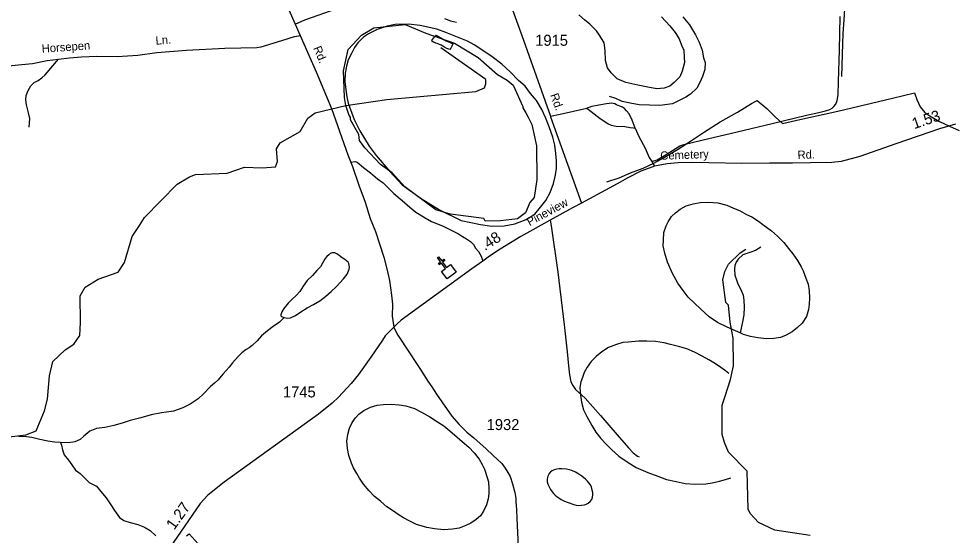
# Model space of a CAD drawing. Extents: x 2206922 to 2357709, y 510027 to 673830.
# Drawn here: x 2306591 to 2317208, y 526957 to 532816 of the extents above; entities that cross this region are included whole.
import ezdxf

# ---------------------------------------------------------------- set-up
doc = ezdxf.new("R2010")
doc.units = 0
for name, color, linetype in [('Exist Cultural Church CELL', 7, 'Continuous'), ('Exist Hydrographic Creek Single Shore', 7, 'Continuous'), ('Exist Hydrographic Misc Water Feature', 7, 'Continuous'), ('Exist Hydrographic Pond Under 1500 Sq Ft', 7, 'Continuous'), ('Exist Road Non-System Type 51', 7, 'Continuous'), ('Exist Road Non-System Type 51 Label', 7, 'Continuous'), ('Exist Road Secondary Mileage Hundredths English Label', 7, 'Continuous'), ('Exist Road Secondary Type 51 Attributed', 7, 'Continuous'), ('Exist Road Secondary Type 51 Label', 7, 'Continuous'), ('Exist Road Secondary Type 51 Number Label', 7, 'Continuous')]:
    doc.layers.add(name, color=color, linetype=linetype)

msp = doc.modelspace()

# ---------------------------------------------------------------- linework, layer by layer
at = {"layer": 'Exist Cultural Church CELL'}
msp.add_lwpolyline([(2311388, 529950), (2311433, 529984), (2311388, 530045), (2311362, 530026), (2311353, 530039), (2311378, 530058), (2311342, 530106), (2311355, 530116), (2311391, 530068), (2311416, 530087), (2311426, 530074), (2311401, 530055), (2311446, 529994), (2311492, 530029), (2311556, 529943), (2311452, 529865)], close=True, dxfattribs=at)
at = {"layer": 'Exist Hydrographic Creek Single Shore'}
msp.add_lwpolyline([(2306388, 528063), (2306671, 528097), (2306788, 528141), (2306885, 528368), (2306917, 528501), (2306939, 528767), (2306979, 528926), (2307119, 529060), (2307218, 529126), (2307284, 529221), (2307291, 529369), (2307287, 529671), (2307345, 529771), (2307494, 529863), (2307718, 529941), (2307791, 530052), (2307880, 530344), (2307962, 530469), (2308019, 530560), (2308390, 530939), (2308530, 531023), (2308597, 531049), (2308955, 531064), (2309154, 531131), (2309354, 531126), (2309504, 531135), (2309528, 531195), (2309518, 531342), (2309559, 531409), (2309783, 531537), (2309873, 531688), (2309955, 531747), (2310304, 531833)], dxfattribs=at)
at = {"layer": 'Exist Hydrographic Misc Water Feature'}
for points in [[(2315975, 533192), (2315957, 532856), (2315945, 532650), (2315936, 532414), (2315930, 532160)], [(2313886, 532837), (2313981, 532736), (2314042, 532661), (2314085, 532588), (2314113, 532516), (2314140, 532460), (2314141, 532378), (2314145, 532318), (2314121, 532220), (2314093, 532158), (2314028, 532093), (2313979, 532051), (2313917, 532028), (2313831, 532021), (2313729, 532038), (2313617, 532061), (2313482, 532093), (2313382, 532134), (2313315, 532204), (2313273, 532259), (2313250, 532343), (2313246, 532455), (2313234, 532544), (2313183, 532630), (2313148, 532680), (2313071, 532755), (2313013, 532802), (2312949, 532861)], [(2314128, 532836), (2314203, 532745), (2314272, 532634), (2314313, 532550), (2314348, 532461), (2314363, 532371), (2314381, 532319), (2314376, 532241), (2314351, 532159), (2314320, 532092), (2314287, 532030), (2314213, 531961), (2314162, 531927), (2314078, 531884), (2314009, 531851), (2313865, 531830), (2313749, 531834), (2313633, 531841), (2313531, 531858), (2313439, 531877), (2313368, 531910), (2313296, 531934)], [(2310343, 531816), (2310372, 531744), (2310398, 531674), (2310460, 531543), (2310566, 531372), (2310649, 531263), (2310803, 531083), (2310944, 530933), (2311158, 530775), (2311367, 530649), (2311610, 530528), (2311831, 530481), (2311959, 530462), (2312099, 530467), (2312222, 530491), (2312350, 530538), (2312447, 530599), (2312512, 530678), (2312571, 530754), (2312622, 530843), (2312661, 530947), (2312680, 531027), (2312693, 531115), (2312694, 531205), (2312688, 531289), (2312676, 531383), (2312653, 531473), (2312610, 531588), (2312569, 531696), (2312528, 531787), (2312465, 531887), (2312400, 531966), (2312337, 532051), (2312263, 532116), (2312168, 532213), (2312073, 532302), (2311964, 532383), (2311857, 532456), (2311761, 532519), (2311682, 532560), (2311552, 532614), (2311439, 532661), (2311335, 532696), (2311145, 532738), (2311014, 532756), (2310863, 532751), (2310773, 532730), (2310657, 532695), (2310562, 532646), (2310504, 532607), (2310439, 532544), (2310402, 532488), (2310366, 532422), (2310329, 532349), (2310312, 532277), (2310295, 532197), (2310292, 532105), (2310299, 532041), (2310314, 531929), (2310329, 531858), (2310343, 531816)], [(2311493, 532482), (2311485, 532466), (2311451, 532477), (2311423, 532495), (2311385, 532517), (2311357, 532528), (2311341, 532534), (2311325, 532540), (2311309, 532546), (2311297, 532552), (2311280, 532561), (2311284, 532577), (2311302, 532600), (2311314, 532616), (2311330, 532630), (2311348, 532620), (2311382, 532599), (2311412, 532579), (2311438, 532565), (2311480, 532550), (2311501, 532540), (2311517, 532532), (2311505, 532504), (2311493, 532482)], [(2313266, 530966), (2313404, 531011), (2313535, 531067), (2313679, 531122), (2313800, 531177), (2313915, 531243), (2314066, 531332), (2314225, 531436), (2314372, 531533), (2314552, 531645), (2314749, 531755), (2314908, 531853), (2314972, 531888), (2315081, 531797), (2315178, 531700), (2315260, 531629), (2315456, 531673), (2315887, 531768), (2316508, 531916), (2316758, 531977), (2316784, 531899), (2316822, 531818), (2316874, 531752), (2316932, 531715), (2317041, 531650), (2317152, 531599), (2317264, 531548)], [(2314778, 529253), (2314724, 529274), (2314631, 529317), (2314521, 529372), (2314427, 529435), (2314330, 529520), (2314255, 529593), (2314188, 529658), (2314131, 529732), (2314069, 529817), (2314012, 529926), (2313952, 530056), (2313923, 530155), (2313904, 530241), (2313909, 530303), (2313912, 530393), (2313938, 530465), (2313961, 530511), (2313998, 530572), (2314044, 530616), (2314097, 530657), (2314165, 530692), (2314245, 530716), (2314326, 530731), (2314419, 530736), (2314523, 530727), (2314625, 530703), (2314701, 530669), (2314769, 530642), (2314850, 530597), (2314912, 530568), (2314987, 530518), (2315037, 530483), (2315135, 530410), (2315200, 530349), (2315273, 530278), (2315326, 530210), (2315376, 530149), (2315429, 530075), (2315472, 530000), (2315494, 529956), (2315525, 529875), (2315548, 529805), (2315561, 529729), (2315564, 529647), (2315562, 529577), (2315553, 529519), (2315532, 529439), (2315483, 529362), (2315427, 529312), (2315370, 529263), (2315302, 529227), (2315234, 529200), (2315161, 529187), (2315077, 529184), (2314977, 529197), (2314894, 529212), (2314817, 529233), (2314778, 529253)], [(2309603, 529427), (2309639, 529419), (2309675, 529424), (2309731, 529448), (2309792, 529493), (2309864, 529536), (2309937, 529575), (2310007, 529617), (2310076, 529670), (2310138, 529721), (2310193, 529775), (2310238, 529824), (2310278, 529864), (2310317, 529919), (2310335, 529957), (2310341, 529975), (2310343, 529999), (2310340, 530021), (2310336, 530039), (2310328, 530053), (2310292, 530086), (2310263, 530104), (2310229, 530132), (2310215, 530139), (2310199, 530151), (2310179, 530159), (2310149, 530161), (2310127, 530152), (2310109, 530138), (2310089, 530120), (2310068, 530096), (2310038, 530043), (2310015, 530003), (2309973, 529961), (2309924, 529902), (2309866, 529848), (2309817, 529783), (2309780, 529723), (2309738, 529676), (2309689, 529632), (2309649, 529590), (2309600, 529529), (2309578, 529491), (2309567, 529459), (2309567, 529445), (2309573, 529437), (2309603, 529427)], [(2315571, 526953), (2315170, 527015), (2314987, 527103), (2314893, 527204), (2314868, 527252), (2314856, 527685), (2314645, 527900), (2314601, 528010), (2314575, 528100), (2314573, 528432), (2314605, 528525), (2314669, 528724), (2314701, 528877), (2314697, 529191), (2314663, 529374), (2314644, 529567), (2314617, 529598), (2314582, 529856), (2314606, 529949), (2314647, 530033), (2314778, 530159), (2314844, 530202)], [(2315012, 530223), (2314952, 530188), (2314886, 530166), (2314809, 530137), (2314755, 530088), (2314731, 530056), (2314718, 530016), (2314712, 529976), (2314719, 529908), (2314738, 529856), (2314750, 529808), (2314787, 529745), (2314813, 529681), (2314818, 529623), (2314825, 529545), (2314820, 529459), (2314805, 529379), (2314789, 529307), (2314778, 529253)], [(2309603, 529427), (2309550, 529373), (2309480, 529326), (2309413, 529277), (2309346, 529218), (2309298, 529164), (2309239, 529109), (2309207, 529081), (2309171, 529063), (2309124, 529026), (2309080, 528986), (2309017, 528913), (2308980, 528865), (2308912, 528788), (2308849, 528715), (2308814, 528681), (2308768, 528643), (2308687, 528562), (2308626, 528505), (2308538, 528444), (2308455, 528403), (2308347, 528366), (2308267, 528353), (2308210, 528347), (2308094, 528323), (2307976, 528290), (2307857, 528257), (2307765, 528230), (2307671, 528201), (2307568, 528180), (2307474, 528167), (2307434, 528154), (2307396, 528136), (2307331, 528081), (2307287, 528043), (2307228, 528018), (2307154, 528006), (2307066, 528009)], [(2314649, 528790), (2314611, 528821), (2314560, 528861), (2314498, 528900), (2314422, 528947), (2314347, 528990), (2314259, 529035), (2314172, 529072), (2314094, 529096), (2313986, 529120), (2313914, 529140), (2313816, 529155), (2313718, 529160), (2313626, 529159), (2313506, 529147), (2313448, 529143), (2313376, 529120), (2313283, 529087), (2313210, 529038), (2313144, 528985), (2313087, 528927), (2313041, 528864), (2313006, 528804), (2312987, 528748), (2312971, 528696), (2312960, 528634), (2312965, 528546), (2312978, 528466), (2312999, 528380), (2313038, 528303), (2313096, 528203), (2313139, 528128), (2313198, 528053), (2313252, 527993), (2313321, 527924), (2313402, 527855), (2313497, 527788), (2313599, 527727), (2313730, 527669), (2313842, 527628), (2313941, 527591), (2314051, 527566), (2314155, 527545), (2314273, 527538), (2314389, 527540), (2314459, 527550), (2314542, 527569), (2314610, 527588), (2314672, 527609)], [(2310733, 527308), (2310695, 527342), (2310628, 527397), (2310566, 527461), (2310505, 527538), (2310458, 527605), (2310426, 527657), (2310391, 527721), (2310368, 527776), (2310338, 527862), (2310321, 527940), (2310314, 528026), (2310327, 528100), (2310346, 528170), (2310376, 528236), (2310413, 528288), (2310450, 528329), (2310506, 528373), (2310584, 528410), (2310657, 528431), (2310729, 528440), (2310823, 528443), (2310907, 528438), (2310983, 528425), (2311081, 528394), (2311162, 528352), (2311256, 528300), (2311345, 528245), (2311414, 528197), (2311484, 528140), (2311565, 528071), (2311625, 528022), (2311698, 527956), (2311760, 527891), (2311817, 527820), (2311852, 527758), (2311878, 527705), (2311907, 527613), (2311922, 527561), (2311925, 527483), (2311926, 527427), (2311918, 527371), (2311899, 527303), (2311865, 527231), (2311830, 527178), (2311781, 527136), (2311721, 527095), (2311663, 527067), (2311590, 527038), (2311514, 527027), (2311414, 527020), (2311308, 527031), (2311222, 527044), (2311106, 527079), (2311029, 527116), (2310959, 527153), (2310908, 527186), (2310834, 527238), (2310768, 527281), (2310733, 527308)], [(2306739, 528065), (2306679, 528074), (2306589, 528077)], [(2307066, 528009), (2306996, 528014), (2306922, 528025), (2306830, 528044), (2306739, 528065)], [(2307066, 528009), (2307078, 527979), (2307087, 527925), (2307107, 527871), (2307156, 527808), (2307192, 527756), (2307235, 527697), (2307287, 527657), (2307344, 527602), (2307389, 527556), (2307473, 527513), (2307522, 527452), (2307582, 527383), (2307637, 527303), (2307676, 527238), (2307735, 527160), (2307783, 527123), (2307855, 527100), (2307941, 527080), (2308018, 527049), (2308084, 527010), (2308145, 526951)], [(2312949, 527648), (2312910, 527674), (2312866, 527691), (2312838, 527699), (2312806, 527707), (2312756, 527712), (2312724, 527712), (2312698, 527707), (2312666, 527699), (2312644, 527689), (2312626, 527677), (2312610, 527658), (2312597, 527628), (2312587, 527596), (2312589, 527564), (2312596, 527538), (2312602, 527520), (2312614, 527499), (2312626, 527477), (2312645, 527451), (2312661, 527431), (2312677, 527413), (2312699, 527398), (2312722, 527380), (2312748, 527364), (2312786, 527344), (2312826, 527327), (2312890, 527304), (2312918, 527300), (2312948, 527296), (2312978, 527297), (2313010, 527301), (2313032, 527309), (2313052, 527321), (2313076, 527340), (2313094, 527364), (2313103, 527390), (2313107, 527414), (2313105, 527442), (2313100, 527468), (2313090, 527506), (2313074, 527533), (2313045, 527569), (2313023, 527593), (2312981, 527626), (2312949, 527648)], [(2308494, 526951), (2308524, 526973), (2308662, 526822)]]:
    msp.add_lwpolyline(points, dxfattribs=at)
at = {"layer": 'Exist Hydrographic Pond Under 1500 Sq Ft'}
for points in [[(2310304, 531833), (2310286, 531924), (2310275, 532226), (2310331, 532468), (2310479, 532628), (2310619, 532712), (2310977, 532750), (2311211, 532651), (2311538, 532539), (2311806, 532376), (2312024, 532185), (2312133, 532120), (2312201, 532064), (2312311, 531822), (2312312, 531806), (2312347, 531748), (2312372, 531700), (2312414, 531616), (2312466, 531376), (2312470, 530992), (2312439, 530790), (2312390, 530733), (2312341, 530616), (2312251, 530547), (2312059, 530522), (2311885, 530519), (2311868, 530551), (2311492, 530598), (2311325, 530647), (2310972, 530909), (2310829, 531067), (2310695, 531163), (2310517, 531353), (2310458, 531436), (2310449, 531504), (2310356, 531668), (2310356, 531701), (2310339, 531720), (2310304, 531833)], [(2310304, 531833), (2310770, 531898), (2311777, 531991), (2311877, 532034), (2311893, 532078), (2311893, 532127), (2311381, 532487)]]:
    msp.add_lwpolyline(points, dxfattribs=at)
at = {"layer": 'Exist Road Non-System Type 51'}
for points in [[(2309727, 532754), (2309837, 532802), (2310282, 532960)], [(2311421, 532817), (2311490, 532794), (2311559, 532777)], [(2313775, 531196), (2313835, 531217), (2313939, 531277), (2314050, 531349), (2314094, 531375), (2314137, 531390), (2314343, 531439), (2314745, 531532), (2315143, 531626), (2315532, 531722), (2315671, 531752), (2315747, 531771), (2315794, 531788), (2315822, 531803), (2315841, 531822), (2315862, 531847), (2315879, 531888), (2315890, 531952), (2315894, 532105), (2315907, 532458), (2315913, 532842)], [(2307043, 532356), (2307167, 532372), (2307302, 532384), (2307476, 532390), (2307707, 532389), (2307941, 532403), (2308159, 532433), (2308495, 532461), (2308931, 532482), (2309294, 532488), (2309342, 532496), (2309577, 532569), (2309639, 532587), (2309684, 532603), (2309724, 532615), (2309783, 532627)], [(2306356, 532271), (2306626, 532295), (2306748, 532310), (2306914, 532342), (2307043, 532356)], [(2306711, 531586), (2306717, 531685), (2306701, 531747), (2306679, 531840), (2306671, 531897), (2306677, 531945), (2306697, 532002), (2306729, 532054), (2306766, 532092), (2306810, 532117), (2306854, 532147), (2306889, 532178), (2307043, 532356)], [(2313588, 531575), (2313554, 531664), (2313518, 531739), (2313488, 531771), (2313467, 531796), (2313441, 531811), (2313413, 531826), (2313375, 531839), (2313354, 531852), (2313337, 531856), (2313320, 531858), (2313262, 531852), (2313175, 531837), (2313096, 531820), (2313039, 531801)], [(2312624, 531710), (2312737, 531735), (2313039, 531801)], [(2313039, 531801), (2313086, 531762), (2313188, 531686), (2313241, 531649), (2313279, 531624), (2313313, 531609), (2313371, 531598), (2313471, 531594), (2313528, 531583), (2313567, 531579), (2313588, 531575)], [(2313588, 531575), (2313630, 531479), (2313699, 531349), (2313747, 531243), (2313775, 531196)], [(2310359, 531190), (2310409, 531196), (2310433, 531188), (2310504, 531129), (2310583, 531067), (2310661, 531001), (2310728, 530953), (2310849, 530834), (2310942, 530755), (2311028, 530678), (2311099, 530621), (2311204, 530556), (2311274, 530516), (2311401, 530466), (2311500, 530417), (2311583, 530377), (2311628, 530346), (2311673, 530320), (2311719, 530288), (2311750, 530255), (2311776, 530215), (2311807, 530174), (2311837, 530121), (2311859, 530066)], [(2313775, 531196), (2313792, 531170), (2313805, 531142)], [(2312621, 530532), (2312634, 530468), (2312710, 529941), (2312779, 529345), (2312813, 529039), (2312830, 528877), (2312842, 528776), (2312855, 528698), (2312879, 528656), (2312911, 528610), (2313021, 528512), (2313193, 528316), (2313384, 528095), (2313511, 527950), (2313565, 527891), (2313614, 527855), (2313631, 527845)]]:
    msp.add_lwpolyline(points, dxfattribs=at)
at = {"layer": 'Exist Road Secondary Type 51 Attributed'}
for points in [[(2309323, 533674), (2309727, 532754), (2309967, 532212), (2310142, 531797), (2310327, 531271), (2310378, 531141), (2310449, 530928), (2310522, 530734), (2310581, 530551), (2310638, 530402), (2310733, 530113), (2310773, 529964), (2310799, 529846), (2310822, 529680), (2310832, 529580), (2310828, 529443), (2310846, 529317)], [(2312092, 533199), (2312299, 532625), (2312624, 531710), (2312627, 531703), (2312976, 530723)], [(2317223, 531620), (2317041, 531566), (2316546, 531397), (2316136, 531254), (2315923, 531196), (2315818, 531186), (2315575, 531180), (2315371, 531176), (2315112, 531176), (2314796, 531174), (2314424, 531181), (2314223, 531184), (2314075, 531181), (2313950, 531171), (2313847, 531152), (2313805, 531142), (2313745, 531122), (2313650, 531086), (2313495, 531007), (2313417, 530961), (2313341, 530919), (2312976, 530723)], [(2312976, 530723), (2312876, 530670), (2312621, 530532), (2312289, 530344), (2312054, 530201), (2311934, 530123), (2311859, 530066), (2311733, 529979), (2310931, 529396), (2310885, 529354), (2310846, 529317)], [(2310846, 529317), (2310751, 529218), (2310721, 529171), (2310586, 528976), (2310445, 528782), (2310363, 528680), (2310221, 528523), (2310148, 528457), (2309992, 528330), (2308924, 527560), (2308735, 527413), (2308648, 527318), (2308344, 526871), (2308307, 526812), (2307735, 525941), (2307002, 524832), (2306594, 524231)], [(2310846, 529317), (2310869, 529270), (2310894, 529227), (2310930, 529170), (2310989, 529084), (2311141, 528849), (2311235, 528706), (2311279, 528639), (2311332, 528559), (2311391, 528469), (2311505, 528308), (2311590, 528212), (2311678, 528127), (2311754, 528063), (2311894, 527939), (2311972, 527867), (2312073, 527769), (2312112, 527718), (2312142, 527668), (2312167, 527622), (2312195, 527542), (2312221, 527440), (2312231, 527373), (2312232, 527333), (2312236, 527297), (2312238, 527247), (2312243, 527147), (2312279, 526436)]]:
    msp.add_lwpolyline(points, dxfattribs=at)

# ---------------------------------------------------------------- texts
at = {"layer": 'Exist Road Non-System Type 51 Label'}
for s, p in [('Ln.', (2308147, 532521)), ('Horsepen', (2306855, 532429))]:
    msp.add_text(s, height=95, rotation=4.0762, dxfattribs=at).set_placement(p)
at = {"layer": 'Exist Road Secondary Mileage Hundredths English Label'}
for s, rotation, p in [('1.53', 18.7328, (2316753, 531562)), ('.48', 32.8045, (2311881, 530180)), ('1.27', 54.3337, (2308355, 527010))]:
    msp.add_text(s, height=125, rotation=rotation, dxfattribs=at).set_placement(p)
at = {"layer": 'Exist Road Secondary Type 51 Label'}
for s, rotation, p in [('Rd.', 292.6688, (2309931, 532483)), ('Rd.', 289.6347, (2312621, 531951)), ('Cemetery', 2.2121, (2313873, 531215)), ('Rd.', 2.1422, (2315431, 531224)), ('Pineview', 28.3367, (2312388, 530462))]:
    msp.add_text(s, height=95, rotation=rotation, dxfattribs=at).set_placement(p)
at = {"layer": 'Exist Road Secondary Type 51 Number Label'}
for s, p in [('1915', (2312452, 532509)), ('1745', (2309589, 528520)), ('1932', (2311901, 528150))]:
    msp.add_text(s, height=125, dxfattribs=at).set_placement(p)

doc.saveas('drawing.dxf')
